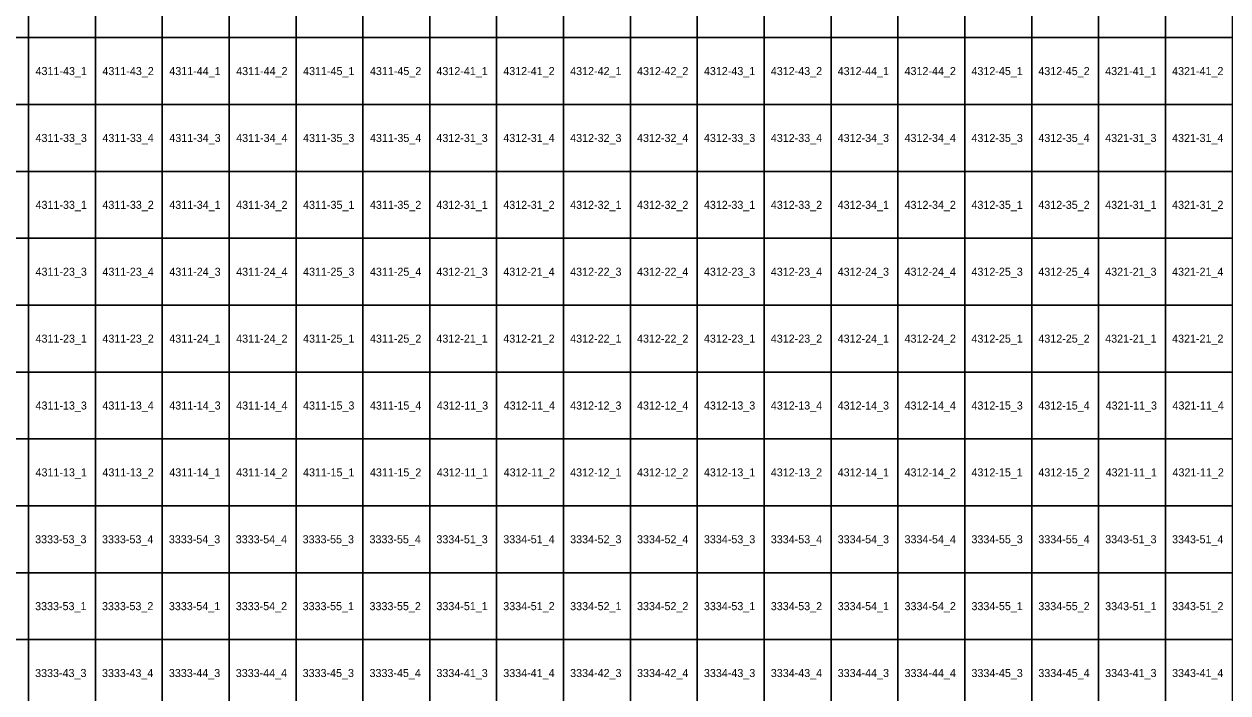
# Model space of a CAD drawing. Extents: x 312500 to 765000, y 172500 to 440000.
# Drawn here: x 509835 to 554835, y 293007 to 318007 of the extents above; entities that cross this region are included whole.
import ezdxf

# ---------------------------------------------------------------- set-up
doc = ezdxf.new("R2010")
doc.units = 0
doc.layers.add('Topo5_ramis_TKS2025', color=7, linetype='Continuous')
doc.layers.add('Topo5_ramis_TKS2025_Nr', color=7, linetype='Continuous')

msp = doc.modelspace()

# ---------------------------------------------------------------- linework, layer by layer
at = {"layer": 'Topo5_ramis_TKS2025'}
for points in [[(507500, 317500), (507500, 320000), (510000, 320000), (510000, 317500), (507500, 317500)], [(510000, 317500), (510000, 320000), (512500, 320000), (512500, 317500), (510000, 317500)], [(512500, 317500), (512500, 320000), (515000, 320000), (515000, 317500), (512500, 317500)], [(515000, 317500), (515000, 320000), (517500, 320000), (517500, 317500), (515000, 317500)], [(517500, 317500), (517500, 320000), (520000, 320000), (520000, 317500), (517500, 317500)], [(520000, 317500), (520000, 320000), (522500, 320000), (522500, 317500), (520000, 317500)], [(522500, 317500), (522500, 320000), (525000, 320000), (525000, 317500), (522500, 317500)], [(525000, 317500), (525000, 320000), (527500, 320000), (527500, 317500), (525000, 317500)], [(527500, 317500), (527500, 320000), (530000, 320000), (530000, 317500), (527500, 317500)], [(530000, 317500), (530000, 320000), (532500, 320000), (532500, 317500), (530000, 317500)], [(532500, 317500), (532500, 320000), (535000, 320000), (535000, 317500), (532500, 317500)], [(535000, 317500), (535000, 320000), (537500, 320000), (537500, 317500), (535000, 317500)], [(537500, 317500), (537500, 320000), (540000, 320000), (540000, 317500), (537500, 317500)], [(540000, 317500), (540000, 320000), (542500, 320000), (542500, 317500), (540000, 317500)], [(542500, 317500), (542500, 320000), (545000, 320000), (545000, 317500), (542500, 317500)], [(545000, 317500), (545000, 320000), (547500, 320000), (547500, 317500), (545000, 317500)], [(547500, 317500), (547500, 320000), (550000, 320000), (550000, 317500), (547500, 317500)], [(550000, 317500), (550000, 320000), (552500, 320000), (552500, 317500), (550000, 317500)], [(552500, 317500), (552500, 320000), (555000, 320000), (555000, 317500), (552500, 317500)], [(507500, 315000), (507500, 317500), (510000, 317500), (510000, 315000), (507500, 315000)], [(510000, 315000), (510000, 317500), (512500, 317500), (512500, 315000), (510000, 315000)], [(512500, 315000), (512500, 317500), (515000, 317500), (515000, 315000), (512500, 315000)], [(515000, 315000), (515000, 317500), (517500, 317500), (517500, 315000), (515000, 315000)], [(517500, 315000), (517500, 317500), (520000, 317500), (520000, 315000), (517500, 315000)], [(520000, 315000), (520000, 317500), (522500, 317500), (522500, 315000), (520000, 315000)], [(522500, 315000), (522500, 317500), (525000, 317500), (525000, 315000), (522500, 315000)], [(525000, 315000), (525000, 317500), (527500, 317500), (527500, 315000), (525000, 315000)], [(527500, 315000), (527500, 317500), (530000, 317500), (530000, 315000), (527500, 315000)], [(530000, 315000), (530000, 317500), (532500, 317500), (532500, 315000), (530000, 315000)], [(532500, 315000), (532500, 317500), (535000, 317500), (535000, 315000), (532500, 315000)], [(535000, 315000), (535000, 317500), (537500, 317500), (537500, 315000), (535000, 315000)], [(537500, 315000), (537500, 317500), (540000, 317500), (540000, 315000), (537500, 315000)], [(540000, 315000), (540000, 317500), (542500, 317500), (542500, 315000), (540000, 315000)], [(542500, 315000), (542500, 317500), (545000, 317500), (545000, 315000), (542500, 315000)], [(545000, 315000), (545000, 317500), (547500, 317500), (547500, 315000), (545000, 315000)], [(547500, 315000), (547500, 317500), (550000, 317500), (550000, 315000), (547500, 315000)], [(550000, 315000), (550000, 317500), (552500, 317500), (552500, 315000), (550000, 315000)], [(552500, 315000), (552500, 317500), (555000, 317500), (555000, 315000), (552500, 315000)], [(507500, 312500), (507500, 315000), (510000, 315000), (510000, 312500), (507500, 312500)], [(510000, 312500), (510000, 315000), (512500, 315000), (512500, 312500), (510000, 312500)], [(512500, 312500), (512500, 315000), (515000, 315000), (515000, 312500), (512500, 312500)], [(515000, 312500), (515000, 315000), (517500, 315000), (517500, 312500), (515000, 312500)], [(517500, 312500), (517500, 315000), (520000, 315000), (520000, 312500), (517500, 312500)], [(520000, 312500), (520000, 315000), (522500, 315000), (522500, 312500), (520000, 312500)], [(522500, 312500), (522500, 315000), (525000, 315000), (525000, 312500), (522500, 312500)], [(525000, 312500), (525000, 315000), (527500, 315000), (527500, 312500), (525000, 312500)], [(527500, 312500), (527500, 315000), (530000, 315000), (530000, 312500), (527500, 312500)], [(530000, 312500), (530000, 315000), (532500, 315000), (532500, 312500), (530000, 312500)], [(532500, 312500), (532500, 315000), (535000, 315000), (535000, 312500), (532500, 312500)], [(535000, 312500), (535000, 315000), (537500, 315000), (537500, 312500), (535000, 312500)], [(537500, 312500), (537500, 315000), (540000, 315000), (540000, 312500), (537500, 312500)], [(540000, 312500), (540000, 315000), (542500, 315000), (542500, 312500), (540000, 312500)], [(542500, 312500), (542500, 315000), (545000, 315000), (545000, 312500), (542500, 312500)], [(545000, 312500), (545000, 315000), (547500, 315000), (547500, 312500), (545000, 312500)], [(547500, 312500), (547500, 315000), (550000, 315000), (550000, 312500), (547500, 312500)], [(550000, 312500), (550000, 315000), (552500, 315000), (552500, 312500), (550000, 312500)], [(552500, 312500), (552500, 315000), (555000, 315000), (555000, 312500), (552500, 312500)], [(507500, 310000), (507500, 312500), (510000, 312500), (510000, 310000), (507500, 310000)], [(510000, 310000), (510000, 312500), (512500, 312500), (512500, 310000), (510000, 310000)], [(512500, 310000), (512500, 312500), (515000, 312500), (515000, 310000), (512500, 310000)], [(515000, 310000), (515000, 312500), (517500, 312500), (517500, 310000), (515000, 310000)], [(517500, 310000), (517500, 312500), (520000, 312500), (520000, 310000), (517500, 310000)], [(520000, 310000), (520000, 312500), (522500, 312500), (522500, 310000), (520000, 310000)], [(522500, 310000), (522500, 312500), (525000, 312500), (525000, 310000), (522500, 310000)], [(525000, 310000), (525000, 312500), (527500, 312500), (527500, 310000), (525000, 310000)], [(527500, 310000), (527500, 312500), (530000, 312500), (530000, 310000), (527500, 310000)], [(530000, 310000), (530000, 312500), (532500, 312500), (532500, 310000), (530000, 310000)], [(532500, 310000), (532500, 312500), (535000, 312500), (535000, 310000), (532500, 310000)], [(535000, 310000), (535000, 312500), (537500, 312500), (537500, 310000), (535000, 310000)], [(537500, 310000), (537500, 312500), (540000, 312500), (540000, 310000), (537500, 310000)], [(540000, 310000), (540000, 312500), (542500, 312500), (542500, 310000), (540000, 310000)], [(542500, 310000), (542500, 312500), (545000, 312500), (545000, 310000), (542500, 310000)], [(545000, 310000), (545000, 312500), (547500, 312500), (547500, 310000), (545000, 310000)], [(547500, 310000), (547500, 312500), (550000, 312500), (550000, 310000), (547500, 310000)], [(550000, 310000), (550000, 312500), (552500, 312500), (552500, 310000), (550000, 310000)], [(552500, 310000), (552500, 312500), (555000, 312500), (555000, 310000), (552500, 310000)], [(507500, 307500), (507500, 310000), (510000, 310000), (510000, 307500), (507500, 307500)], [(510000, 307500), (510000, 310000), (512500, 310000), (512500, 307500), (510000, 307500)], [(512500, 307500), (512500, 310000), (515000, 310000), (515000, 307500), (512500, 307500)], [(515000, 307500), (515000, 310000), (517500, 310000), (517500, 307500), (515000, 307500)], [(517500, 307500), (517500, 310000), (520000, 310000), (520000, 307500), (517500, 307500)], [(520000, 307500), (520000, 310000), (522500, 310000), (522500, 307500), (520000, 307500)], [(522500, 307500), (522500, 310000), (525000, 310000), (525000, 307500), (522500, 307500)], [(525000, 307500), (525000, 310000), (527500, 310000), (527500, 307500), (525000, 307500)], [(527500, 307500), (527500, 310000), (530000, 310000), (530000, 307500), (527500, 307500)], [(530000, 307500), (530000, 310000), (532500, 310000), (532500, 307500), (530000, 307500)], [(532500, 307500), (532500, 310000), (535000, 310000), (535000, 307500), (532500, 307500)], [(535000, 307500), (535000, 310000), (537500, 310000), (537500, 307500), (535000, 307500)], [(537500, 307500), (537500, 310000), (540000, 310000), (540000, 307500), (537500, 307500)], [(540000, 307500), (540000, 310000), (542500, 310000), (542500, 307500), (540000, 307500)], [(542500, 307500), (542500, 310000), (545000, 310000), (545000, 307500), (542500, 307500)], [(545000, 307500), (545000, 310000), (547500, 310000), (547500, 307500), (545000, 307500)], [(547500, 307500), (547500, 310000), (550000, 310000), (550000, 307500), (547500, 307500)], [(550000, 307500), (550000, 310000), (552500, 310000), (552500, 307500), (550000, 307500)], [(552500, 307500), (552500, 310000), (555000, 310000), (555000, 307500), (552500, 307500)], [(507500, 305000), (507500, 307500), (510000, 307500), (510000, 305000), (507500, 305000)], [(510000, 305000), (510000, 307500), (512500, 307500), (512500, 305000), (510000, 305000)], [(512500, 305000), (512500, 307500), (515000, 307500), (515000, 305000), (512500, 305000)], [(515000, 305000), (515000, 307500), (517500, 307500), (517500, 305000), (515000, 305000)], [(517500, 305000), (517500, 307500), (520000, 307500), (520000, 305000), (517500, 305000)], [(520000, 305000), (520000, 307500), (522500, 307500), (522500, 305000), (520000, 305000)], [(522500, 305000), (522500, 307500), (525000, 307500), (525000, 305000), (522500, 305000)], [(525000, 305000), (525000, 307500), (527500, 307500), (527500, 305000), (525000, 305000)], [(527500, 305000), (527500, 307500), (530000, 307500), (530000, 305000), (527500, 305000)], [(530000, 305000), (530000, 307500), (532500, 307500), (532500, 305000), (530000, 305000)], [(532500, 305000), (532500, 307500), (535000, 307500), (535000, 305000), (532500, 305000)], [(535000, 305000), (535000, 307500), (537500, 307500), (537500, 305000), (535000, 305000)], [(537500, 305000), (537500, 307500), (540000, 307500), (540000, 305000), (537500, 305000)], [(540000, 305000), (540000, 307500), (542500, 307500), (542500, 305000), (540000, 305000)], [(542500, 305000), (542500, 307500), (545000, 307500), (545000, 305000), (542500, 305000)], [(545000, 305000), (545000, 307500), (547500, 307500), (547500, 305000), (545000, 305000)], [(547500, 305000), (547500, 307500), (550000, 307500), (550000, 305000), (547500, 305000)], [(550000, 305000), (550000, 307500), (552500, 307500), (552500, 305000), (550000, 305000)], [(552500, 305000), (552500, 307500), (555000, 307500), (555000, 305000), (552500, 305000)], [(507500, 302500), (507500, 305000), (510000, 305000), (510000, 302500), (507500, 302500)], [(510000, 302500), (510000, 305000), (512500, 305000), (512500, 302500), (510000, 302500)], [(512500, 302500), (512500, 305000), (515000, 305000), (515000, 302500), (512500, 302500)], [(515000, 302500), (515000, 305000), (517500, 305000), (517500, 302500), (515000, 302500)], [(517500, 302500), (517500, 305000), (520000, 305000), (520000, 302500), (517500, 302500)], [(520000, 302500), (520000, 305000), (522500, 305000), (522500, 302500), (520000, 302500)], [(522500, 302500), (522500, 305000), (525000, 305000), (525000, 302500), (522500, 302500)], [(525000, 302500), (525000, 305000), (527500, 305000), (527500, 302500), (525000, 302500)], [(527500, 302500), (527500, 305000), (530000, 305000), (530000, 302500), (527500, 302500)], [(530000, 302500), (530000, 305000), (532500, 305000), (532500, 302500), (530000, 302500)], [(532500, 302500), (532500, 305000), (535000, 305000), (535000, 302500), (532500, 302500)], [(535000, 302500), (535000, 305000), (537500, 305000), (537500, 302500), (535000, 302500)], [(537500, 302500), (537500, 305000), (540000, 305000), (540000, 302500), (537500, 302500)], [(540000, 302500), (540000, 305000), (542500, 305000), (542500, 302500), (540000, 302500)], [(542500, 302500), (542500, 305000), (545000, 305000), (545000, 302500), (542500, 302500)], [(545000, 302500), (545000, 305000), (547500, 305000), (547500, 302500), (545000, 302500)], [(547500, 302500), (547500, 305000), (550000, 305000), (550000, 302500), (547500, 302500)], [(550000, 302500), (550000, 305000), (552500, 305000), (552500, 302500), (550000, 302500)], [(552500, 302500), (552500, 305000), (555000, 305000), (555000, 302500), (552500, 302500)], [(507500, 300000), (507500, 302500), (510000, 302500), (510000, 300000), (507500, 300000)], [(510000, 300000), (510000, 302500), (512500, 302500), (512500, 300000), (510000, 300000)], [(512500, 300000), (512500, 302500), (515000, 302500), (515000, 300000), (512500, 300000)], [(515000, 300000), (515000, 302500), (517500, 302500), (517500, 300000), (515000, 300000)], [(517500, 300000), (517500, 302500), (520000, 302500), (520000, 300000), (517500, 300000)], [(520000, 300000), (520000, 302500), (522500, 302500), (522500, 300000), (520000, 300000)], [(522500, 300000), (522500, 302500), (525000, 302500), (525000, 300000), (522500, 300000)], [(525000, 300000), (525000, 302500), (527500, 302500), (527500, 300000), (525000, 300000)], [(527500, 300000), (527500, 302500), (530000, 302500), (530000, 300000), (527500, 300000)], [(530000, 300000), (530000, 302500), (532500, 302500), (532500, 300000), (530000, 300000)], [(532500, 300000), (532500, 302500), (535000, 302500), (535000, 300000), (532500, 300000)], [(535000, 300000), (535000, 302500), (537500, 302500), (537500, 300000), (535000, 300000)], [(537500, 300000), (537500, 302500), (540000, 302500), (540000, 300000), (537500, 300000)], [(540000, 300000), (540000, 302500), (542500, 302500), (542500, 300000), (540000, 300000)], [(542500, 300000), (542500, 302500), (545000, 302500), (545000, 300000), (542500, 300000)], [(545000, 300000), (545000, 302500), (547500, 302500), (547500, 300000), (545000, 300000)], [(547500, 300000), (547500, 302500), (550000, 302500), (550000, 300000), (547500, 300000)], [(550000, 300000), (550000, 302500), (552500, 302500), (552500, 300000), (550000, 300000)], [(552500, 300000), (552500, 302500), (555000, 302500), (555000, 300000), (552500, 300000)], [(507500, 297500), (507500, 300000), (510000, 300000), (510000, 297500), (507500, 297500)], [(510000, 297500), (510000, 300000), (512500, 300000), (512500, 297500), (510000, 297500)], [(512500, 297500), (512500, 300000), (515000, 300000), (515000, 297500), (512500, 297500)], [(515000, 297500), (515000, 300000), (517500, 300000), (517500, 297500), (515000, 297500)], [(517500, 297500), (517500, 300000), (520000, 300000), (520000, 297500), (517500, 297500)], [(520000, 297500), (520000, 300000), (522500, 300000), (522500, 297500), (520000, 297500)], [(522500, 297500), (522500, 300000), (525000, 300000), (525000, 297500), (522500, 297500)], [(525000, 297500), (525000, 300000), (527500, 300000), (527500, 297500), (525000, 297500)], [(527500, 297500), (527500, 300000), (530000, 300000), (530000, 297500), (527500, 297500)], [(530000, 297500), (530000, 300000), (532500, 300000), (532500, 297500), (530000, 297500)], [(532500, 297500), (532500, 300000), (535000, 300000), (535000, 297500), (532500, 297500)], [(535000, 297500), (535000, 300000), (537500, 300000), (537500, 297500), (535000, 297500)], [(537500, 297500), (537500, 300000), (540000, 300000), (540000, 297500), (537500, 297500)], [(540000, 297500), (540000, 300000), (542500, 300000), (542500, 297500), (540000, 297500)], [(542500, 297500), (542500, 300000), (545000, 300000), (545000, 297500), (542500, 297500)], [(545000, 297500), (545000, 300000), (547500, 300000), (547500, 297500), (545000, 297500)], [(547500, 297500), (547500, 300000), (550000, 300000), (550000, 297500), (547500, 297500)], [(550000, 297500), (550000, 300000), (552500, 300000), (552500, 297500), (550000, 297500)], [(552500, 297500), (552500, 300000), (555000, 300000), (555000, 297500), (552500, 297500)], [(507500, 295000), (507500, 297500), (510000, 297500), (510000, 295000), (507500, 295000)], [(510000, 295000), (510000, 297500), (512500, 297500), (512500, 295000), (510000, 295000)], [(512500, 295000), (512500, 297500), (515000, 297500), (515000, 295000), (512500, 295000)], [(515000, 295000), (515000, 297500), (517500, 297500), (517500, 295000), (515000, 295000)], [(517500, 295000), (517500, 297500), (520000, 297500), (520000, 295000), (517500, 295000)], [(520000, 295000), (520000, 297500), (522500, 297500), (522500, 295000), (520000, 295000)], [(522500, 295000), (522500, 297500), (525000, 297500), (525000, 295000), (522500, 295000)], [(525000, 295000), (525000, 297500), (527500, 297500), (527500, 295000), (525000, 295000)], [(527500, 295000), (527500, 297500), (530000, 297500), (530000, 295000), (527500, 295000)], [(530000, 295000), (530000, 297500), (532500, 297500), (532500, 295000), (530000, 295000)], [(532500, 295000), (532500, 297500), (535000, 297500), (535000, 295000), (532500, 295000)], [(535000, 295000), (535000, 297500), (537500, 297500), (537500, 295000), (535000, 295000)], [(537500, 295000), (537500, 297500), (540000, 297500), (540000, 295000), (537500, 295000)], [(540000, 295000), (540000, 297500), (542500, 297500), (542500, 295000), (540000, 295000)], [(542500, 295000), (542500, 297500), (545000, 297500), (545000, 295000), (542500, 295000)], [(545000, 295000), (545000, 297500), (547500, 297500), (547500, 295000), (545000, 295000)], [(547500, 295000), (547500, 297500), (550000, 297500), (550000, 295000), (547500, 295000)], [(550000, 295000), (550000, 297500), (552500, 297500), (552500, 295000), (550000, 295000)], [(552500, 295000), (552500, 297500), (555000, 297500), (555000, 295000), (552500, 295000)], [(507500, 292500), (507500, 295000), (510000, 295000), (510000, 292500), (507500, 292500)], [(510000, 292500), (510000, 295000), (512500, 295000), (512500, 292500), (510000, 292500)], [(512500, 292500), (512500, 295000), (515000, 295000), (515000, 292500), (512500, 292500)], [(515000, 292500), (515000, 295000), (517500, 295000), (517500, 292500), (515000, 292500)], [(517500, 292500), (517500, 295000), (520000, 295000), (520000, 292500), (517500, 292500)], [(520000, 292500), (520000, 295000), (522500, 295000), (522500, 292500), (520000, 292500)], [(522500, 292500), (522500, 295000), (525000, 295000), (525000, 292500), (522500, 292500)], [(525000, 292500), (525000, 295000), (527500, 295000), (527500, 292500), (525000, 292500)], [(527500, 292500), (527500, 295000), (530000, 295000), (530000, 292500), (527500, 292500)], [(530000, 292500), (530000, 295000), (532500, 295000), (532500, 292500), (530000, 292500)], [(532500, 292500), (532500, 295000), (535000, 295000), (535000, 292500), (532500, 292500)], [(535000, 292500), (535000, 295000), (537500, 295000), (537500, 292500), (535000, 292500)], [(537500, 292500), (537500, 295000), (540000, 295000), (540000, 292500), (537500, 292500)], [(540000, 292500), (540000, 295000), (542500, 295000), (542500, 292500), (540000, 292500)], [(542500, 292500), (542500, 295000), (545000, 295000), (545000, 292500), (542500, 292500)], [(545000, 292500), (545000, 295000), (547500, 295000), (547500, 292500), (545000, 292500)], [(547500, 292500), (547500, 295000), (550000, 295000), (550000, 292500), (547500, 292500)], [(550000, 292500), (550000, 295000), (552500, 295000), (552500, 292500), (550000, 292500)], [(552500, 292500), (552500, 295000), (555000, 295000), (555000, 292500), (552500, 292500)]]:
    msp.add_lwpolyline(points, dxfattribs=at)

# ---------------------------------------------------------------- texts
at = {"layer": 'Topo5_ramis_TKS2025_Nr'}
for s, p in [('4311-43_1', (510264, 316100)), ('4311-43_2', (512764, 316100)), ('4311-44_1', (515264, 316100)), ('4311-44_2', (517764, 316100)), ('4311-45_1', (520264, 316100)), ('4311-45_2', (522764, 316100)), ('4312-41_1', (525248, 316100)), ('4312-41_2', (527748, 316100)), ('4312-42_1', (530248, 316100)), ('4312-42_2', (532748, 316100)), ('4312-43_1', (535248, 316100)), ('4312-43_2', (537748, 316100)), ('4312-44_1', (540248, 316100)), ('4312-44_2', (542748, 316100)), ('4312-45_1', (545248, 316100)), ('4312-45_2', (547748, 316100)), ('4321-41_1', (550248, 316100)), ('4321-41_2', (552748, 316100)), ('4311-33_3', (510264, 313600)), ('4311-33_4', (512764, 313600)), ('4311-34_3', (515264, 313600)), ('4311-34_4', (517764, 313600)), ('4311-35_3', (520264, 313600)), ('4311-35_4', (522764, 313600)), ('4312-31_3', (525248, 313600)), ('4312-31_4', (527748, 313600)), ('4312-32_3', (530248, 313600)), ('4312-32_4', (532748, 313600)), ('4312-33_3', (535248, 313600)), ('4312-33_4', (537748, 313600)), ('4312-34_3', (540248, 313600)), ('4312-34_4', (542748, 313600)), ('4312-35_3', (545248, 313600)), ('4312-35_4', (547748, 313600)), ('4321-31_3', (550248, 313600)), ('4321-31_4', (552748, 313600)), ('4311-33_1', (510264, 311100)), ('4311-33_2', (512764, 311100)), ('4311-34_1', (515264, 311100)), ('4311-34_2', (517764, 311100)), ('4311-35_1', (520264, 311100)), ('4311-35_2', (522764, 311100)), ('4312-31_1', (525248, 311100)), ('4312-31_2', (527748, 311100)), ('4312-32_1', (530248, 311100)), ('4312-32_2', (532748, 311100)), ('4312-33_1', (535248, 311100)), ('4312-33_2', (537748, 311100)), ('4312-34_1', (540248, 311100)), ('4312-34_2', (542748, 311100)), ('4312-35_1', (545248, 311100)), ('4312-35_2', (547748, 311100)), ('4321-31_1', (550248, 311100)), ('4321-31_2', (552748, 311100)), ('4311-23_3', (510264, 308600)), ('4311-23_4', (512764, 308600)), ('4311-24_3', (515264, 308600)), ('4311-24_4', (517764, 308600)), ('4311-25_3', (520264, 308600)), ('4311-25_4', (522764, 308600)), ('4312-21_3', (525248, 308600)), ('4312-21_4', (527748, 308600)), ('4312-22_3', (530248, 308600)), ('4312-22_4', (532748, 308600)), ('4312-23_3', (535248, 308600)), ('4312-23_4', (537748, 308600)), ('4312-24_3', (540248, 308600)), ('4312-24_4', (542748, 308600)), ('4312-25_3', (545248, 308600)), ('4312-25_4', (547748, 308600)), ('4321-21_3', (550248, 308600)), ('4321-21_4', (552748, 308600)), ('4311-23_1', (510264, 306100)), ('4311-23_2', (512764, 306100)), ('4311-24_1', (515264, 306100)), ('4311-24_2', (517764, 306100)), ('4311-25_1', (520264, 306100)), ('4311-25_2', (522764, 306100)), ('4312-21_1', (525248, 306100)), ('4312-21_2', (527748, 306100)), ('4312-22_1', (530248, 306100)), ('4312-22_2', (532748, 306100)), ('4312-23_1', (535248, 306100)), ('4312-23_2', (537748, 306100)), ('4312-24_1', (540248, 306100)), ('4312-24_2', (542748, 306100)), ('4312-25_1', (545248, 306100)), ('4312-25_2', (547748, 306100)), ('4321-21_1', (550248, 306100)), ('4321-21_2', (552748, 306100)), ('4311-13_3', (510264, 303600)), ('4311-13_4', (512764, 303600)), ('4311-14_3', (515264, 303600)), ('4311-14_4', (517764, 303600)), ('4311-15_3', (520264, 303600)), ('4311-15_4', (522764, 303600)), ('4312-11_3', (525264, 303600)), ('4312-11_4', (527764, 303600)), ('4312-12_3', (530248, 303600)), ('4312-12_4', (532748, 303600)), ('4312-13_3', (535248, 303600)), ('4312-13_4', (537748, 303600)), ('4312-14_3', (540248, 303600)), ('4312-14_4', (542748, 303600)), ('4312-15_3', (545248, 303600)), ('4312-15_4', (547748, 303600)), ('4321-11_3', (550264, 303600)), ('4321-11_4', (552764, 303600)), ('4311-13_1', (510264, 301100)), ('4311-13_2', (512764, 301100)), ('4311-14_1', (515264, 301100)), ('4311-14_2', (517764, 301100)), ('4311-15_1', (520264, 301100)), ('4311-15_2', (522764, 301100)), ('4312-11_1', (525264, 301100)), ('4312-11_2', (527764, 301100)), ('4312-12_1', (530248, 301100)), ('4312-12_2', (532748, 301100)), ('4312-13_1', (535248, 301100)), ('4312-13_2', (537748, 301100)), ('4312-14_1', (540248, 301100)), ('4312-14_2', (542748, 301100)), ('4312-15_1', (545248, 301100)), ('4312-15_2', (547748, 301100)), ('4321-11_1', (550264, 301100)), ('4321-11_2', (552764, 301100)), ('3333-53_3', (510248, 298600)), ('3333-53_4', (512748, 298600)), ('3333-54_3', (515248, 298600)), ('3333-54_4', (517748, 298600)), ('3333-55_3', (520248, 298600)), ('3333-55_4', (522748, 298600)), ('3334-51_3', (525248, 298600)), ('3334-51_4', (527748, 298600)), ('3334-52_3', (530248, 298600)), ('3334-52_4', (532748, 298600)), ('3334-53_3', (535248, 298600)), ('3334-53_4', (537748, 298600)), ('3334-54_3', (540248, 298600)), ('3334-54_4', (542748, 298600)), ('3334-55_3', (545248, 298600)), ('3334-55_4', (547748, 298600)), ('3343-51_3', (550248, 298600)), ('3343-51_4', (552748, 298600)), ('3333-53_1', (510248, 296100)), ('3333-53_2', (512748, 296100)), ('3333-54_1', (515248, 296100)), ('3333-54_2', (517748, 296100)), ('3333-55_1', (520248, 296100)), ('3333-55_2', (522748, 296100)), ('3334-51_1', (525248, 296100)), ('3334-51_2', (527748, 296100)), ('3334-52_1', (530248, 296100)), ('3334-52_2', (532748, 296100)), ('3334-53_1', (535248, 296100)), ('3334-53_2', (537748, 296100)), ('3334-54_1', (540248, 296100)), ('3334-54_2', (542748, 296100)), ('3334-55_1', (545248, 296100)), ('3334-55_2', (547748, 296100)), ('3343-51_1', (550248, 296100)), ('3343-51_2', (552748, 296100)), ('3333-43_3', (510248, 293600)), ('3333-43_4', (512748, 293600)), ('3333-44_3', (515248, 293600)), ('3333-44_4', (517748, 293600)), ('3333-45_3', (520248, 293600)), ('3333-45_4', (522748, 293600)), ('3334-41_3', (525248, 293600)), ('3334-41_4', (527748, 293600)), ('3334-42_3', (530248, 293600)), ('3334-42_4', (532748, 293600)), ('3334-43_3', (535248, 293600)), ('3334-43_4', (537748, 293600)), ('3334-44_3', (540248, 293600)), ('3334-44_4', (542748, 293600)), ('3334-45_3', (545248, 293600)), ('3334-45_4', (547748, 293600)), ('3343-41_3', (550248, 293600)), ('3343-41_4', (552748, 293600))]:
    msp.add_text(s, height=300, dxfattribs=at).set_placement(p)

doc.saveas('drawing.dxf')
